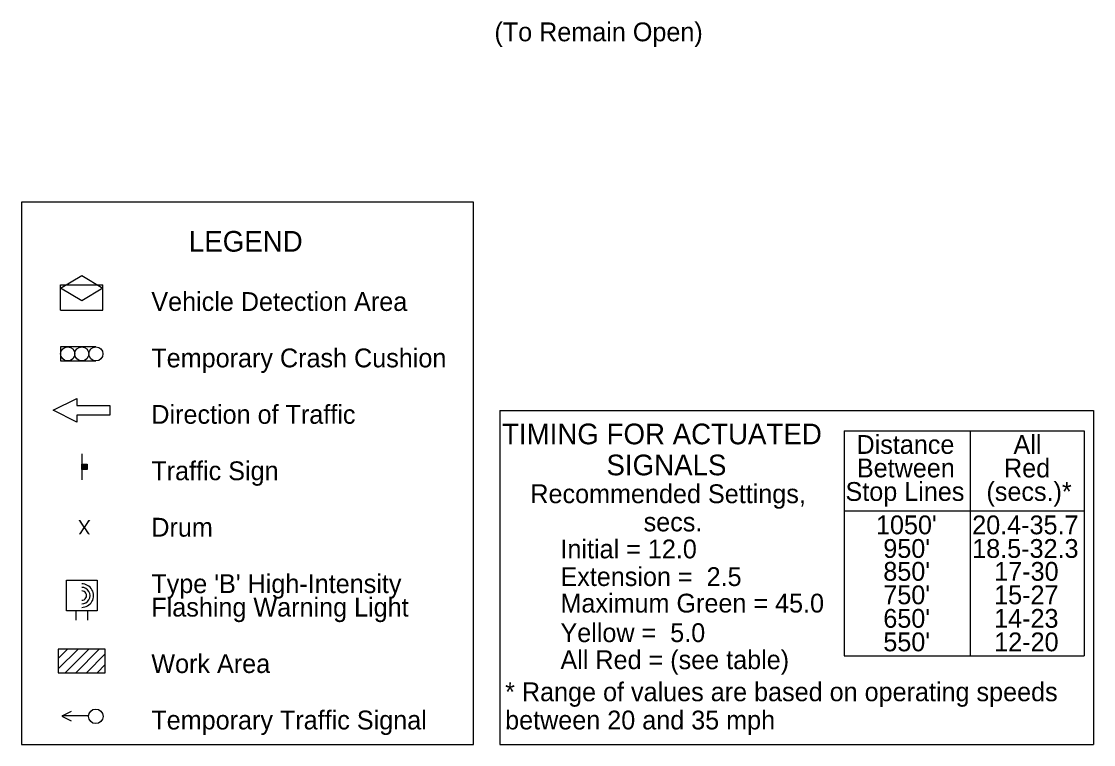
# Model space of a CAD drawing. Extents: x 10133 to 81668, y 4692 to 11018.
# Drawn here: x 21008 to 22147, y 5499 to 6268 of the extents above; entities that cross this region are included whole.
import ezdxf

# ---------------------------------------------------------------- set-up
doc = ezdxf.new("R2010")
doc.units = 0
for name, color, linetype in [('dsnCellElements', 7, 'Continuous'), ('DsnShtRevisedText', 7, 'Continuous'), ('SheetBorder', 7, 'Continuous'), ('ShtPlotIdentification', 7, 'Continuous')]:
    doc.layers.add(name, color=color, linetype=linetype)

msp = doc.modelspace()

# ---------------------------------------------------------------- linework, layer by layer
at = {"layer": 'dsnCellElements'}
for p, q in [((21049.2, 5960.9), (21049.2, 5987.9)), ((21049.2, 5987.9), (21094.2, 5987.9)), ((21094.2, 5960.9), (21094.2, 5987.9)), ((21049.2, 5960.9), (21094.2, 5960.9)), ((21049.2, 5921.9), (21049.2, 5906.9)), ((21086.7, 5921.9), (21049.2, 5921.9)), ((21049.2, 5906.9), (21086.7, 5906.9)), ((21516.1, 5854.1), (21516.1, 5499)), ((21516.1, 5854.1), (22147.2, 5854.1)), ((22147.2, 5854.1), (22147.2, 5499)), ((21071.7, 5808.1), (21071.7, 5780.6)), ((21072.1, 5791.6), (21072.1, 5797.2)), ((21072.4, 5797.2), (21072.4, 5791.6)), ((21072.6, 5791.6), (21072.6, 5797.2)), ((21072.9, 5797.2), (21072.9, 5791.6)), ((21073.1, 5791.6), (21073.1, 5797.2)), ((21073.3, 5797.2), (21073.3, 5791.6)), ((21073.7, 5791.6), (21073.7, 5797.2)), ((21073.9, 5797.2), (21073.9, 5791.6)), ((21074.1, 5791.6), (21074.1, 5797.2)), ((21074.5, 5797.2), (21074.5, 5791.6)), ((21074.8, 5791.6), (21074.8, 5797.2)), ((21075.3, 5797.2), (21075.3, 5791.6)), ((21075.5, 5791.6), (21075.5, 5797.2)), ((21075.9, 5797.2), (21075.9, 5791.6)), ((21076.1, 5791.6), (21076.1, 5797.2)), ((21076.4, 5797.2), (21076.4, 5791.6)), ((21076.7, 5791.6), (21076.7, 5797.2)), ((21077, 5797.2), (21077, 5791.6)), ((21065.4, 5641.2), (21065.4, 5631.2)), ((21077.9, 5641.2), (21077.9, 5631.2)), ((21046.7, 5579.4), (21067.7, 5600.4)), ((21046.7, 5590.7), (21056.4, 5600.4)), ((21054, 5575.4), (21079, 5600.4)), ((21065.3, 5575.4), (21090.3, 5600.4)), ((21076.6, 5575.4), (21096.7, 5595.5)), ((21087.9, 5575.4), (21096.7, 5584.2)), ((21078.8, 5529.4), (21050.9, 5529.4)), ((21516.1, 5499), (22147.2, 5499))]:
    msp.add_line(p, q, dxfattribs=at)
for points in [[(21007.5, 5499), (21488.2, 5499), (21488.2, 6075.7), (21007.5, 6075.7)], [(21101.4, 5859.4), (21101.4, 5849.4), (21066.4, 5849.4), (21066.4, 5841.9), (21041.4, 5854.4), (21066.4, 5866.9), (21066.4, 5859.4)], [(21071.8, 5791.6), (21071.8, 5797.2), (21077.4, 5797.2), (21077.4, 5791.6)], [(21055.4, 5641.2), (21055.4, 5673.7), (21087.9, 5673.7), (21087.9, 5641.2)], [(21046.7, 5575.4), (21096.7, 5575.4), (21096.7, 5600.4), (21046.7, 5600.4)]]:
    msp.add_lwpolyline(points, close=True, dxfattribs=at)
msp.add_lwpolyline([(21060.5, 5534.2), (21050.5, 5529.2), (21060.5, 5524.2)], dxfattribs=at)
for centre, radius in [((21056.7, 5914.4), 7.5), ((21056.7, 5914.4), 7.5), ((21071.7, 5914.4), 7.5), ((21071.7, 5914.4), 7.5), ((21086.7, 5914.4), 7.5), ((21086.7, 5914.4), 7.5), ((21086.6, 5529), 7.74)]:
    msp.add_circle(centre, radius, dxfattribs=at)
for radius in [12.5, 12.5, 8.75, 5]:
    msp.add_arc((21071.7, 5657.4), radius, 269.4041, 90.5445, dxfattribs=at)
at = {"layer": 'DsnShtRevisedText'}
for p, q in [((21882, 5832.6), (21882, 5593.5)), ((21882, 5832.6), (22137.2, 5832.6)), ((22016, 5832.6), (22016, 5593.5)), ((22137.2, 5832.6), (22137.2, 5593.5)), ((21882, 5747.6), (22137.2, 5747.6)), ((21882, 5593.5), (22137.2, 5593.5))]:
    msp.add_line(p, q, dxfattribs=at)
at = {"layer": 'ShtPlotIdentification'}
msp.add_lwpolyline([(21049.2, 5984.4), (21071.7, 5997.9), (21094.2, 5984.4), (21071.7, 5970.9)], close=True, dxfattribs=at)

# ---------------------------------------------------------------- texts
at = {"layer": 'dsnCellElements'}
msp.add_text('X', height=15, rotation=180, dxfattribs=at).set_placement((21081.1, 5737.7))
at = {"layer": 'DsnShtRevisedText'}
for s, height, p in [('LEGEND', 22, (21185.5, 6023.1)), ('Vehicle Detection Area', 20, (21145.6, 5960.1)), ('Temporary Crash Cushion', 20, (21145.6, 5900.1)), ('Direction of Traffic', 20, (21145.6, 5840.1)), ('TIMING FOR ACTUATED ', 22, (21518.4, 5818.3)), ('Distance', 20, (21895.2, 5808.1)), ('All', 20, (22062.1, 5808.1)), ('Traffic Sign', 20, (21145.6, 5780.1)), ('SIGNALS', 22, (21629.4, 5785.3)), ('Between', 20, (21895.6, 5783.1)), ('Red', 20, (22052, 5783.1)), ('Stop Lines', 20, (21883.5, 5758.1)), (' (secs.)*', 20, (22025.9, 5758.1)), ('Recommended Settings, ', 20, (21548.5, 5755.7)), ('Drum', 20, (21145.6, 5720.1)), ('secs.', 20, (21668.9, 5725.7)), ("1050'", 20, (21915.9, 5722.6)), ('20.4-35.7', 20, (22018.2, 5722.6)), ('Initial = 12.0', 20, (21580.5, 5697)), ("950'", 20, (21923.7, 5697.5)), ('18.5-32.3', 20, (22018.2, 5697.5)), ('Extension =  2.5', 20, (21580.5, 5667.6)), ("850'", 20, (21923.7, 5673.2)), ('17-30', 20, (22041.6, 5673.2)), ("Type 'B' High-Intensity", 20, (21145.6, 5660.1)), ("750'", 20, (21923.7, 5648.2)), ('15-27', 20, (22041.5, 5648.2)), ('Flashing Warning Light', 20, (21145.6, 5635.1)), ('Maximum Green = 45.0', 20, (21580.5, 5639.4)), ("650'", 20, (21923.7, 5623.2)), ('14-23', 20, (22041.5, 5623.2)), ('Yellow =  5.0', 20, (21580.5, 5608)), ("550'", 20, (21923.7, 5598.2)), ('12-20', 20, (22041.6, 5598.2)), ('Work Area', 20, (21145.6, 5575.1)), ('All Red = (see table)', 20, (21580.5, 5579.2)), ('* Range of values are based on operating speeds', 20, (21521.7, 5545.1)), ('Temporary Traffic Signal', 20, (21145.6, 5515.1)), ('between 20 and 35 mph', 20, (21521.7, 5515.1))]:
    msp.add_text(s, height=height, dxfattribs=at).set_placement(p)
at = {"layer": 'SheetBorder'}
msp.add_text('(To Remain Open)', height=20, dxfattribs=at).set_placement((21510.3, 6246.8))

doc.saveas('drawing.dxf')
